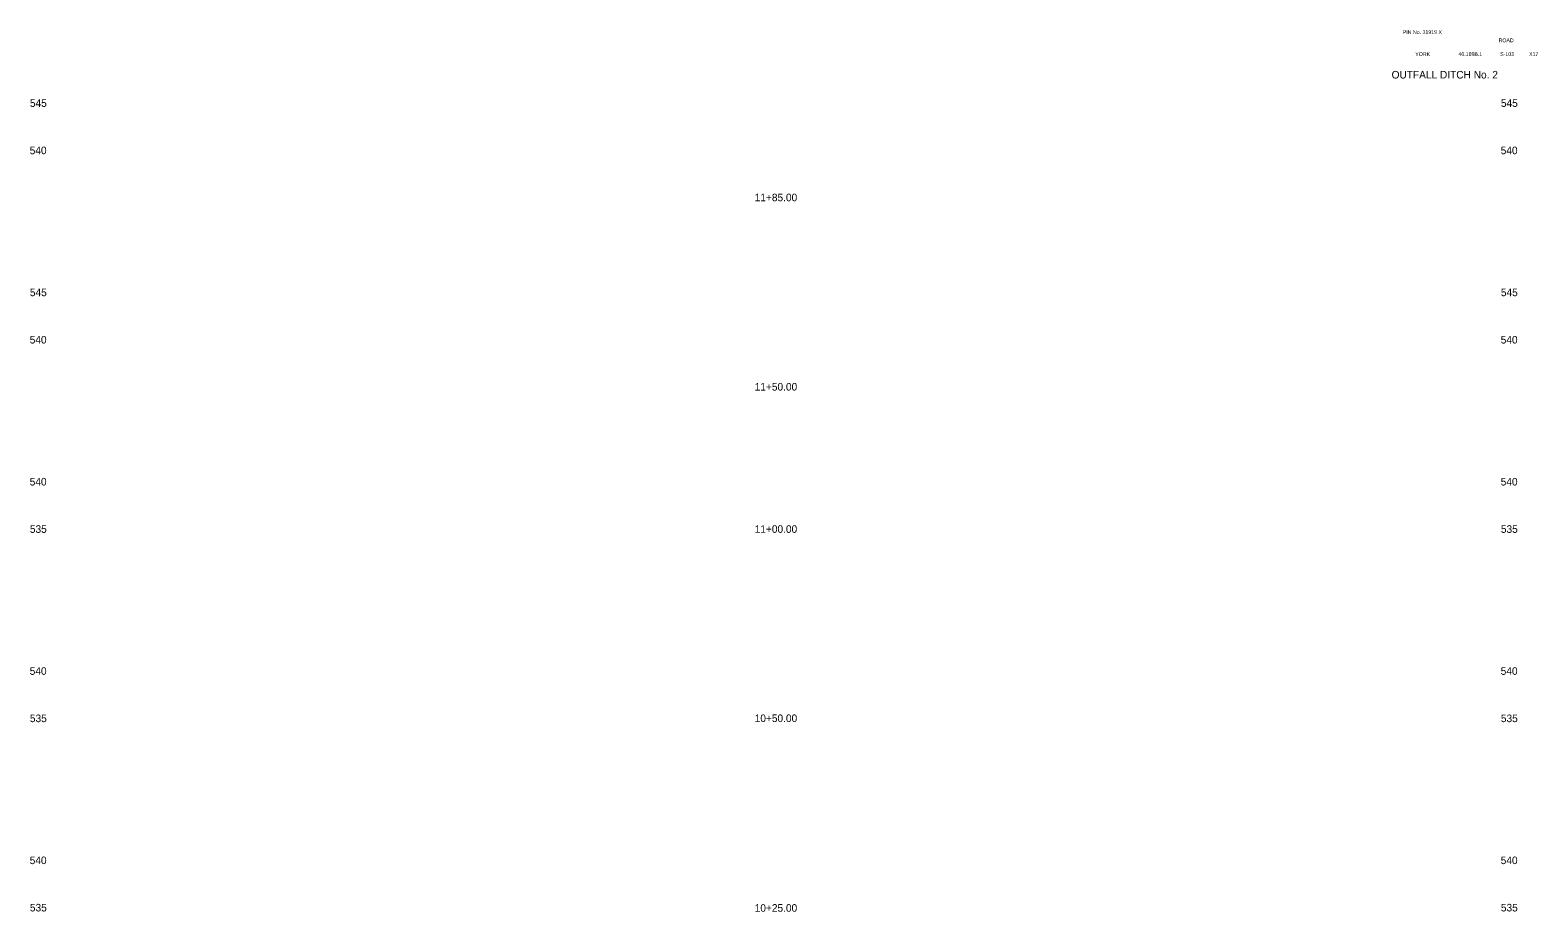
# Model space of a CAD drawing. Extents: x 1001 to 1161, y 1010 to 1103.
import ezdxf

# ---------------------------------------------------------------- set-up
doc = ezdxf.new("R2010")
doc.units = 0
for name, color, linetype in [('RD_GPK_XS_Cell', 7, 'Continuous'), ('RD_XS_ExGround', 7, 'Continuous'), ('RD_XS_TX_Elev_EX', 7, 'Continuous')]:
    doc.layers.add(name, color=color, linetype=linetype)

msp = doc.modelspace()

# ---------------------------------------------------------------- texts
at = {"layer": 'RD_GPK_XS_Cell'}
for s, p in [('545', (1001.15, 1095.1)), ('545', (1156.65, 1095.1)), ('540', (1001.13, 1090.1)), ('540', (1156.63, 1090.1)), ('545', (1001.15, 1075.1)), ('545', (1156.65, 1075.1)), ('540', (1001.13, 1070.1)), ('540', (1156.63, 1070.1)), ('540', (1001.13, 1055.1)), ('540', (1156.63, 1055.1)), ('535', (1001.15, 1050.1)), ('535', (1156.65, 1050.1)), ('540', (1001.13, 1035.1)), ('540', (1156.63, 1035.1)), ('535', (1001.15, 1030.1)), ('535', (1156.65, 1030.1)), ('540', (1001.13, 1015.1)), ('540', (1156.63, 1015.1)), ('535', (1001.15, 1010.1)), ('535', (1156.65, 1010.1))]:
    msp.add_text(s, height=0.8, dxfattribs=at).set_placement(p)
at = {"layer": 'RD_XS_ExGround'}
for s, p in [('11+85.00', (1077.77, 1085.13)), ('11+50.00', (1077.77, 1065.13)), ('11+00.00', (1077.77, 1050.1)), ('10+50.00', (1077.77, 1030.11)), ('10+25.00', (1077.77, 1010.07))]:
    msp.add_text(s, height=0.8, dxfattribs=at).set_placement(p)
at = {"layer": 'RD_XS_TX_Elev_EX'}
for s, height, p in [('PIN No. 31919 X', 0.4, (1146.28, 1102.8)), ('ROAD', 0.4, (1156.41, 1101.93)), ('YORK', 0.4, (1147.6, 1100.48)), ('46.169B.1', 0.4, (1152.16, 1100.48)), ('S-103', 0.4, (1156.57, 1100.48)), ('X17', 0.4, (1159.63, 1100.48)), ('OUTFALL DITCH No. 2', 0.8, (1145.1, 1098.1))]:
    msp.add_text(s, height=height, dxfattribs=at).set_placement(p)

doc.saveas('drawing.dxf')
